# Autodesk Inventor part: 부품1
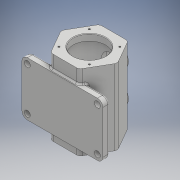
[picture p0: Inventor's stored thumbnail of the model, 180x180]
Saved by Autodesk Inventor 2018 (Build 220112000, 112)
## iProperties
Created: 2021-06
Part Number: 부품1
Material: 일반
Document SubType Name: Modeling
Designer: 1class 18
Density: 1 g/cm^3
Appearance: 기본값
Mass: 553.882 g
Surface Area: 1102.24 cm^2
Volume: 553.882 cm^3
Author: 1class 18
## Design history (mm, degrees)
sketch "스케치1"
  geometry: L1 (-26.183, 45.505)-(26.317, 45.428); L2 (26.317, 45.428)-(52.5, -0.077); L3 (52.5, -0.077)-(26.183, -45.505); L4 (26.183, -45.505)-(-26.317, -45.428); L5 (-26.317, -45.428)-(-52.5, 0.077); L6 (-52.5, 0.077)-(-26.183, 45.505); 2 further points
  constraints: 12 end point, 13 other
  dimensions: "d1" = 90.93267 distance between parallel lines of L2 L5; "d2" = 45.46633 distance from line of point (0, 0) L2; "d3" = 45.46633 distance from line of point (0, 0) L3
extrude "돌출1" new body sketch "스케치1" stored distance "d4" = 140; taper "d5" = 0 deg
sketch "스케치2"
  geometry: L1 (0.077, 70)-(0.077, -70) reference; L2 (0.077, 70)-(30.077, 70); L3 (30.077, 70)-(30.077, 58); L4 (30.077, 58)-(0.077, 58); L5 (0.077, 58)-(0.077, 70); L6 (0.077, 58)-(37.577, 58); L7 (37.577, 58)-(37.577, -58); L8 (37.577, -58)-(0.077, -58); L9 (0.077, -58)-(0.077, 58); L10 (0.077, -70)-(45.505, -70) reference; L11 (0.077, -58)-(30.077, -58); L12 (30.077, -58)-(30.077, -70); L13 (30.077, -70)-(0.077, -70); L14 (0.077, -70)-(0.077, -58); 1 further point
  constraints: 24 end point, 6 parallel, 3 horizontal, 3 perpendicular, 2 point on line
  dimensions: "d6" = 12 distance of L2.end L3.end; "d7" = 12 distance of L11.end L12.end; "d8" = 60 diameter of L3 L1; "d9" = 75 diameter of L7 L1
revolve "회전1" sketch "스케치2" stored, may be unused: angle "d10" = 90 deg
sketch "스케치3" dims "d11" = 80
  geometry: 3 further points
  constraints: 1 coincident, 1 vertical alignment, 2 other
hole "구멍1" sketch "스케치3" at (0, 40) diameter "d12" = 3.242; stored, may be unused: countersink angle "d16" = 90 deg, drill point angle "d18" = 118 deg; dims "d13" = 8, "d14" = 4, "d15" = 2, "d17" = 10
node "작업 평면1"
sketch "스케치4"
  geometry: L1 (-26.317, 70)-(26.183, 70) reference; C1 r 20 at (0, 30); 1 further point
  constraints: 1 centre point
  dimensions: "d23" = 40 distance from line of L1 C1.centre; "d25" = 40 diameter of C1; "d27" = 30 distance of point (0, 0) C1.centre
extrude "돌출2" join sketch "스케치4" stored distance "d28" = 8; taper "d29" = 0 deg
hole "구멍2" diameter "d32" = 30; stored, may be unused: countersink angle "d36" = 90 deg, drill point angle "d38" = 0 deg; dims "d30" = 10, "d31" = 10, "d33" = 8, "d34" = 4, "d35" = 2, "d37" = 8
hole "구멍3" diameter "d41" = 25; stored, may be unused: countersink angle "d45" = 90 deg, drill point angle "d47" = 0 deg; dims "d39" = 10, "d40" = 10, "d42" = 8, "d43" = 4, "d44" = 2, "d46" = 8
node "작업 평면2"
sketch "스케치5"
  geometry: L1 (26.183, 70)-(52.5, 70) reference; L2 (75, 45)-(-75, 45); L3 (-75, 45)-(-75, -55); L4 (-75, -55)-(75, -55); L5 (75, -55)-(75, 45); C1 r 12.5 at (0, 30) reference; 1 further point
  constraints: 8 end point, 2 parallel, 1 horizontal, 1 perpendicular
  dimensions: "d52" = 150 distance of L4.end L3.end; "d53" = 100 distance of L3.end L2.end; "d54" = 25 distance between parallel lines of L1 L2; "d55" = 75 distance from line of L3 point (0, 0)
extrude "돌출3" join sketch "스케치5" distance "d56" = 12; taper "d57" = 0 deg
fillet "모깎기1" dims "d58" = 10
hole "구멍4" diameter "d61" = 11; stored, may be unused: countersink angle "d65" = 90 deg, drill point angle "d67" = 0 deg; dims "d59" = 10, "d60" = 10, "d62" = 8, "d63" = 4, "d64" = 2, "d66" = 8
hole "구멍5" diameter "d73" = 11; stored, may be unused: countersink angle "d77" = 90 deg, drill point angle "d79" = 0 deg; dims "d71" = 10, "d72" = 10, "d74" = 8, "d75" = 4, "d76" = 2, "d78" = 8
fillet "모깎기2" dims "d83" = 8
chamfer "모따기1" distance "d84" = 1; stored, may be unused: second distance "d85" = 2, angle "d86" = 45 deg
fillet "모깎기3" dims "d87" = 5
fillet "모깎기4" dims "d88" = 3
sketch "스케치6"
  geometry: L1 (-65, -45)-(-32.326, -45) reference; L2 (-75, 45)-(-75, -35) reference; 2 further points
  constraints: 1 other
  dimensions: "d89" = 50 distance from line of L1 point (-61, 5); "d90" = 14 distance from line of L2 point (-61, 5)
feature "엠보싱1" sketch "스케치6" dims "d1" = 90.93267, "d2" = 45.46633, "d3" = 45.46633, "d6" = 12, "d7" = 12, "d8" = 60, "d9" = 75, "d91" = 0.5, "d92" = 0
sketch "스케치7" dims "d93" = 80
  geometry: L1 (0, 0)-(0, 70.159); L2 (0, 0)-(-46.367, 46.367); 2 further points
  constraints: 4 end point, 1 coincident, 1 point on line, 1 vertical, 3 other
  dimensions: "d101" = 45 deg angle of L2 L1
hole "구멍7" sketch "스케치7" at (-28.284, 28.284) diameter "d102" = 3.242; stored, may be unused: countersink angle "d106" = 90 deg, drill point angle "d108" = 118 deg; dims "d103" = 8, "d104" = 4, "d105" = 2, "d107" = 10
node "솔리드1"
pattern_circular "원형 패턴1" dims angle "d20" = 360 deg
mirror "미러1"
pattern_linear "직사각형 패턴1" dims "d70" = 130
pattern_linear "직사각형 패턴2" dims "d82" = 130
pattern_circular "원형 패턴2" dims angle "d110" = 360 deg
other parameters: "d22" = 52.5
